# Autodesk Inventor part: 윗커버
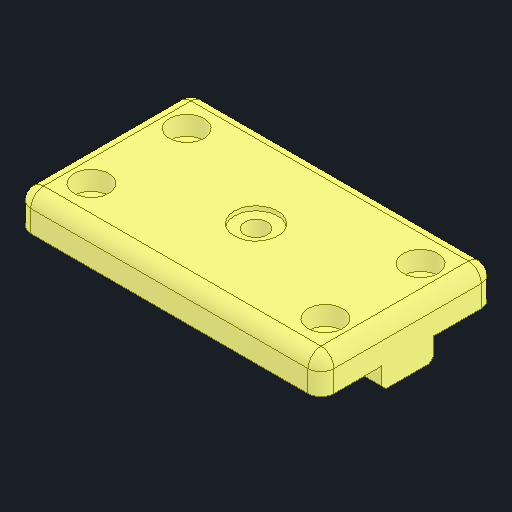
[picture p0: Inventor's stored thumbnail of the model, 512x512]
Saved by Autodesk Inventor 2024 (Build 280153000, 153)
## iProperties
Created: 2025-02
Part Number: 윗커버
Material: 강철, 주조
Document SubType Name: Modeling
Designer: kh_501
Density: 7.85 g/cm^3
Appearance: 기본값
Author: jhkim
Sending System: Autodesk Inventor 2025
Preprocessor: ST-DEVELOPER v20
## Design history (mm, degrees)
feature "솔리드1"
node "솔리드2"
